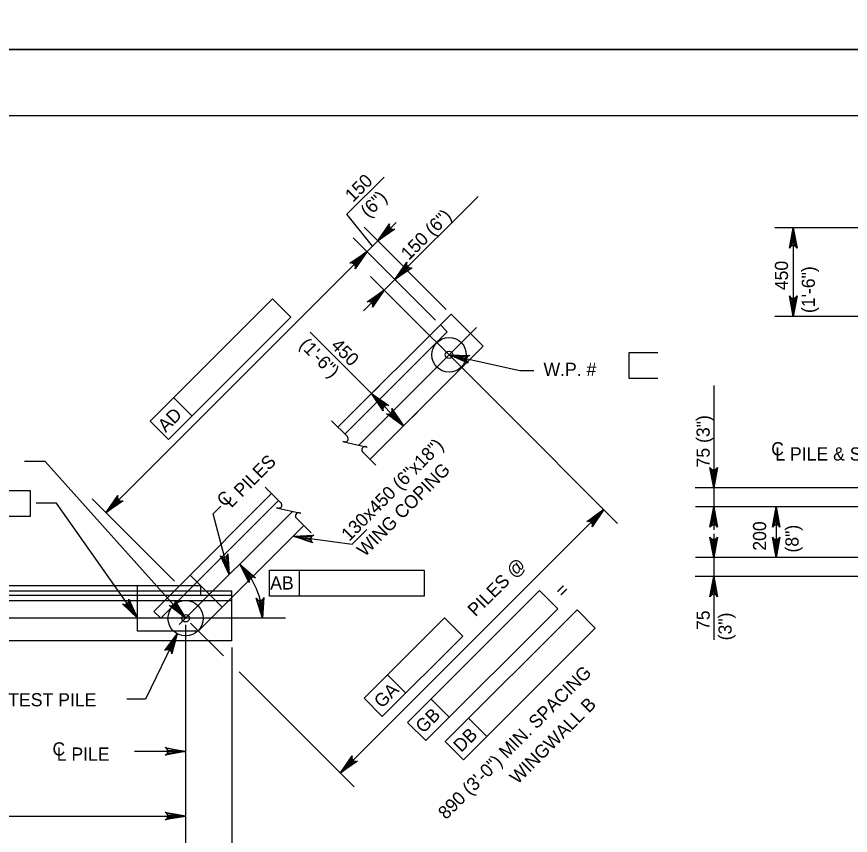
# Model space of a CAD drawing. Extents: x 635440 to 640306, y 296653 to 298484.
# Drawn here: x 638835.6 to 639025.5, y 297662.4 to 297849 of the extents above; entities that cross this region are included whole.
import ezdxf

# ---------------------------------------------------------------- set-up
doc = ezdxf.new("R2010")
doc.units = 0
for name, color, linetype in [('2', 7, 'Continuous'), ('4', 7, 'Continuous'), ('5', 7, 'Continuous'), ('PLT-BNDY', 7, 'Continuous')]:
    doc.layers.add(name, color=color, linetype=linetype)

msp = doc.modelspace()

# ---------------------------------------------------------------- linework, layer by layer
at = {"layer": '2'}
for p, q in [((638475.46, 297826.46), (639261.46, 297826.46)), ((638908.79, 297755.39), (638934.56, 297781.16)), ((638934.56, 297781.16), (638941.87, 297773.85)), ((638916.1, 297748.08), (638941.87, 297773.85)), ((638872.65, 297719.24), (638893.68, 297740.28)), ((638876.93, 297708.91), (638900.99, 297732.97)), ((638882.39, 297714.37), (638875.08, 297721.68)), ((638872.65, 297719.24), (638626.07, 297719.24)), ((638863.11, 297708.91), (638863.11, 297719.24)), ((638884.63, 297706.7), (638884.63, 297716.61)), ((638876.93, 297708.91), (638863.11, 297708.91)), ((638884.63, 297706.7), (638615.23, 297706.7))]:
    msp.add_line(p, q, dxfattribs=at)
msp.add_lwpolyline([(638863.11, 297711.86), (638844.66, 297738.11), (638840.05, 297738.11)], dxfattribs=at)
msp.add_lwpolyline([(638863.11, 297711.86), (638861.61, 297714.42), (638861.21, 297714.14)], close=True, dxfattribs=at)
at = {"layer": '4'}
for p, q in [((638910.35, 297753.82), (638933.69, 297777.16)), ((638932.13, 297778.72), (638933.69, 297777.16)), ((638868.4, 297711.86), (638895.24, 297738.71)), ((638615.23, 297718.1), (638884.63, 297718.1)), ((638872.65, 297719.24), (638866.83, 297713.43)), ((638877.54, 297719.24), (638872.65, 297719.24)), ((638877.54, 297717.03), (638877.54, 297719.24)), ((638884.63, 297716.61), (638884.63, 297718.1)), ((638884.63, 297717.03), (638615.23, 297717.03)), ((638615.23, 297715.88), (638884.63, 297715.88)), ((638868.4, 297711.86), (638866.83, 297713.43))]:
    msp.add_line(p, q, dxfattribs=at)
for points in [[(638934.1, 297771.88), (638950.22, 297768.33), (638953.44, 297768.33)], [(638874.08, 297711.86), (638842.11, 297747.55), (638837.34, 297747.55)], [(638898.58, 297730.56), (638911.99, 297728.73), (638915.35, 297732.08)]]:
    msp.add_lwpolyline(points, dxfattribs=at)
for points in [[(638934.1, 297771.88), (638936.93, 297771), (638937.03, 297771.49)], [(638898.58, 297730.56), (638901.47, 297729.92), (638901.54, 297730.4)], [(638874.08, 297711.86), (638872.29, 297714.22), (638871.93, 297713.9)]]:
    msp.add_lwpolyline(points, close=True, dxfattribs=at)
for centre, radius in [((638934.1, 297771.88), 3.94), ((638874.08, 297711.86), 4.02)]:
    msp.add_circle(centre, radius, dxfattribs=at)
at = {"layer": '5'}
for p, q in [((638910.85, 297803.91), (638919.35, 297812.41)), ((638921.78, 297789.07), (638940.7, 297807.99)), ((638916.64, 297796.64), (638910.85, 297803.91)), ((638917.86, 297797.86), (638922.03, 297802.04)), ((638933.47, 297782.25), (638914.73, 297801)), ((639034.02, 297800.84), (639008.36, 297800.84)), ((639012.51, 297800.84), (639012.51, 297780.65)), ((638931.04, 297779.81), (638912.29, 297798.56)), ((638912.99, 297792.99), (638917.86, 297797.86)), ((638855.94, 297735.95), (638915.42, 297795.43)), ((638913.33, 297793.34), (638911.25, 297791.25)), ((638931.04, 297779.81), (638918.65, 297792.2)), ((638916.21, 297789.77), (638945.21, 297760.77)), ((638921.78, 297789.07), (638919.34, 297786.63)), ((638919.34, 297786.63), (638914.63, 297781.92)), ((638866, 297756.8), (638893.84, 297784.64)), ((638893.84, 297784.64), (638898.02, 297780.46)), ((638870.18, 297752.62), (638898.02, 297780.46)), ((639029.65, 297780.65), (639008.36, 297780.65)), ((638916.44, 297763.04), (638902.45, 297777.03)), ((638913.53, 297751.31), (638940.33, 297778.12)), ((638975.11, 297772.39), (638981.71, 297772.39)), ((638975.11, 297766.49), (638975.11, 297772.39)), ((638917.04, 297763.64), (638919.57, 297766.17)), ((638981.71, 297766.49), (638975.11, 297766.49)), ((638994.42, 297764.9), (638994.42, 297737.24)), ((638871.35, 297762.15), (638875.52, 297757.97)), ((638923.74, 297755.73), (638916.44, 297763.04)), ((638945.21, 297760.77), (638972.5, 297733.48)), ((638924.34, 297756.33), (638926.88, 297758.86)), ((638866, 297756.8), (638870.18, 297752.62)), ((638907.35, 297756.83), (638910.93, 297753.24)), ((638914.37, 297749.81), (638917.42, 297746.75)), ((638797.48, 297740.95), (638838.69, 297740.95)), ((638838.69, 297740.95), (638838.69, 297735.04)), ((638892.23, 297741.73), (638895.81, 297738.14)), ((639029.65, 297741.57), (638990.17, 297741.57)), ((638871.56, 297720.33), (638852.81, 297739.08)), ((638880.38, 297735.66), (638882.11, 297737.39)), ((639057.05, 297737.24), (638990.25, 297737.24)), ((639008.64, 297737.24), (639008.64, 297725.7)), ((638872.62, 297710.4), (638898.42, 297736.2)), ((638884.03, 297721.81), (638880.38, 297735.66)), ((638909.35, 297676.59), (638969.37, 297736.61)), ((638994.42, 297736.2), (638994.42, 297732.04)), ((638838.69, 297735.04), (638797.48, 297735.04)), ((638899.25, 297734.71), (638902.65, 297731.31)), ((638871.56, 297720.33), (638859.17, 297732.72)), ((638994.42, 297731.12), (638994.42, 297730.73)), ((638994.42, 297730.9), (638994.42, 297721.38)), ((639046.96, 297725.7), (638990.25, 297725.7)), ((638994.42, 297725.7), (638994.42, 297706.95)), ((638893.17, 297722.83), (638928.47, 297722.83)), ((638893.17, 297716.92), (638893.17, 297722.83)), ((638900.01, 297716.92), (638900.01, 297722.83)), ((638928.47, 297722.83), (638928.47, 297716.92)), ((639029.65, 297721.38), (638990.17, 297721.38)), ((638924.62, 297688.13), (638954.69, 297718.2)), ((638954.69, 297718.2), (638958.86, 297714.02)), ((638928.47, 297716.92), (638893.17, 297716.92)), ((638928.79, 297683.96), (638958.86, 297714.02)), ((638933.19, 297683.74), (638963.26, 297713.81)), ((638963.26, 297713.81), (638967.43, 297709.63)), ((638896.85, 297711.86), (638603.94, 297711.86)), ((638875.17, 297710.77), (638882.69, 297703.26)), ((638914.73, 297693.62), (638933.07, 297711.96)), ((638933.07, 297711.96), (638937.25, 297707.79)), ((638874.08, 297710.32), (638874.08, 297650.07)), ((638937.37, 297679.57), (638967.43, 297709.63)), ((638872.19, 297708.31), (638864.92, 297693.42)), ((638918.9, 297689.44), (638937.25, 297707.79)), ((638884.63, 297705.16), (638884.63, 297635.92)), ((638886.3, 297699.64), (638912.48, 297673.46)), ((638920.08, 297698.97), (638924.25, 297694.79)), ((638864.92, 297693.42), (638860.72, 297693.42)), ((638914.73, 297693.62), (638918.9, 297689.44)), ((638929.97, 297693.48), (638934.14, 297689.3)), ((638924.62, 297688.13), (638928.79, 297683.96)), ((638938.54, 297689.09), (638942.71, 297684.91)), ((638933.19, 297683.74), (638937.37, 297679.57)), ((638874.08, 297681.51), (638862.46, 297681.51)), ((638624.44, 297666.75), (638874.08, 297666.75))]:
    msp.add_line(p, q, dxfattribs=at)
for points in [[(638917.86, 297797.86), (638920.54, 297801.78), (638920.46, 297801.35), (638920.55, 297801), (638920.73, 297800.74), (638920.99, 297800.55), (638921.34, 297800.46), (638921.77, 297800.54), (638917.86, 297797.86), (638921.34, 297800.46), (638920.99, 297800.55), (638917.86, 297797.86), (638920.73, 297800.74), (638920.55, 297801), (638917.86, 297797.86), (638920.46, 297801.35)], [(639012.51, 297800.84), (639013.39, 297796.18), (639013.14, 297796.54), (639012.83, 297796.72), (639012.51, 297796.77), (639012.2, 297796.72), (639011.89, 297796.54), (639011.64, 297796.18), (639012.51, 297800.84), (639011.89, 297796.54), (639012.2, 297796.72), (639012.51, 297800.84), (639012.51, 297796.77), (639012.83, 297796.72), (639012.51, 297800.84), (639013.14, 297796.54)], [(638915.42, 297795.43), (638912.74, 297791.51), (638912.82, 297791.94), (638912.73, 297792.3), (638912.55, 297792.55), (638912.29, 297792.74), (638911.94, 297792.83), (638911.51, 297792.75), (638915.42, 297795.43), (638911.94, 297792.83), (638912.29, 297792.74), (638915.42, 297795.43), (638912.55, 297792.55), (638912.73, 297792.3), (638915.42, 297795.43), (638912.82, 297791.94)], [(638921.78, 297789.07), (638924.46, 297792.98), (638924.38, 297792.56), (638924.47, 297792.2), (638924.65, 297791.95), (638924.91, 297791.76), (638925.26, 297791.67), (638925.69, 297791.75), (638921.78, 297789.07), (638925.26, 297791.67), (638924.91, 297791.76), (638921.78, 297789.07), (638924.65, 297791.95), (638924.47, 297792.2), (638921.78, 297789.07), (638924.38, 297792.56)], [(638919.34, 297786.63), (638916.67, 297782.72), (638916.74, 297783.15), (638916.65, 297783.5), (638916.47, 297783.76), (638916.21, 297783.94), (638915.86, 297784.03), (638915.43, 297783.96), (638919.34, 297786.63), (638915.86, 297784.03), (638916.21, 297783.94), (638919.34, 297786.63), (638916.47, 297783.76), (638916.65, 297783.5), (638919.34, 297786.63), (638916.74, 297783.15)], [(639012.51, 297780.65), (639011.64, 297785.31), (639011.89, 297784.95), (639012.2, 297784.77), (639012.51, 297784.71), (639012.83, 297784.77), (639013.14, 297784.95), (639013.39, 297785.31), (639012.51, 297780.65), (639013.14, 297784.95), (639012.83, 297784.77), (639012.51, 297780.65), (639012.51, 297784.71), (639012.2, 297784.77), (639012.51, 297780.65), (639011.89, 297784.95)], [(638934.1, 297771.88), (638938.84, 297771.73), (638938.43, 297771.57), (638938.18, 297771.3), (638938.06, 297771.01), (638938.05, 297770.69), (638938.16, 297770.34), (638938.46, 297770.02), (638934.1, 297771.88), (638938.16, 297770.34), (638938.05, 297770.69), (638934.1, 297771.88), (638938.06, 297771.01), (638938.18, 297771.3), (638934.1, 297771.88), (638938.43, 297771.57)], [(638916.44, 297763.04), (638920.35, 297760.36), (638919.92, 297760.44), (638919.57, 297760.35), (638919.31, 297760.16), (638919.13, 297759.91), (638919.04, 297759.55), (638919.12, 297759.12), (638916.44, 297763.04), (638919.04, 297759.55), (638919.13, 297759.91), (638916.44, 297763.04), (638919.31, 297760.16), (638919.57, 297760.35), (638916.44, 297763.04), (638919.92, 297760.44)], [(638923.74, 297755.73), (638919.83, 297758.41), (638920.26, 297758.33), (638920.61, 297758.42), (638920.87, 297758.6), (638921.05, 297758.86), (638921.15, 297759.21), (638921.07, 297759.64), (638923.74, 297755.73), (638921.15, 297759.21), (638921.05, 297758.86), (638923.74, 297755.73), (638920.87, 297758.6), (638920.61, 297758.42), (638923.74, 297755.73), (638920.26, 297758.33)], [(638910.25, 297752.06), (638909.9, 297752.13), (638915.44, 297750.87), (638915.07, 297750.96)], [(638994.42, 297741.57), (638993.55, 297746.23), (638993.79, 297745.87), (638994.11, 297745.68), (638994.42, 297745.63), (638994.73, 297745.68), (638995.04, 297745.87), (638995.29, 297746.23), (638994.42, 297741.57), (638995.04, 297745.87), (638994.73, 297745.68), (638994.42, 297741.57), (638994.42, 297745.63), (638994.11, 297745.68), (638994.42, 297741.57), (638993.79, 297745.87)], [(638855.94, 297735.95), (638858.62, 297739.86), (638858.54, 297739.43), (638858.63, 297739.08), (638858.82, 297738.82), (638859.08, 297738.64), (638859.43, 297738.55), (638859.86, 297738.63), (638855.94, 297735.95), (638859.43, 297738.55), (638859.08, 297738.64), (638855.94, 297735.95), (638858.82, 297738.82), (638858.63, 297739.08), (638855.94, 297735.95), (638858.54, 297739.43)], [(638994.42, 297737.24), (638995.29, 297732.58), (638995.04, 297732.94), (638994.73, 297733.12), (638994.42, 297733.18), (638994.11, 297733.12), (638993.79, 297732.94), (638993.55, 297732.58), (638994.42, 297737.24), (638993.79, 297732.94), (638994.11, 297733.12), (638994.42, 297737.24), (638994.42, 297733.18), (638994.73, 297733.12), (638994.42, 297737.24), (638995.04, 297732.94)], [(639008.64, 297737.24), (639009.51, 297732.58), (639009.27, 297732.94), (639008.95, 297733.12), (639008.64, 297733.18), (639008.33, 297733.12), (639008.02, 297732.94), (639007.77, 297732.58), (639008.64, 297737.24), (639008.02, 297732.94), (639008.33, 297733.12), (639008.64, 297737.24), (639008.64, 297733.18), (639008.95, 297733.12), (639008.64, 297737.24), (639009.27, 297732.94)], [(638895.13, 297736.95), (638894.78, 297737.03), (638900.32, 297735.77), (638899.95, 297735.85)], [(638969.37, 297736.61), (638966.69, 297732.69), (638966.77, 297733.12), (638966.68, 297733.48), (638966.5, 297733.73), (638966.24, 297733.92), (638965.89, 297734.01), (638965.46, 297733.93), (638969.37, 297736.61), (638965.89, 297734.01), (638966.24, 297733.92), (638969.37, 297736.61), (638966.5, 297733.73), (638966.68, 297733.48), (638969.37, 297736.61), (638966.77, 297733.12)], [(638898.58, 297730.56), (638903.32, 297730.8), (638902.93, 297730.6), (638902.7, 297730.31), (638902.61, 297730.01), (638902.62, 297729.69), (638902.76, 297729.36), (638903.08, 297729.07), (638898.58, 297730.56), (638902.76, 297729.36), (638902.62, 297729.69), (638898.58, 297730.56), (638902.61, 297730.01), (638902.7, 297730.31), (638898.58, 297730.56), (638902.93, 297730.6)], [(638994.42, 297725.7), (638993.55, 297730.37), (638993.79, 297730.01), (638994.11, 297729.82), (638994.42, 297729.77), (638994.73, 297729.82), (638995.04, 297730.01), (638995.29, 297730.37), (638994.42, 297725.7), (638995.04, 297730.01), (638994.73, 297729.82), (638994.42, 297725.7), (638994.42, 297729.77), (638994.11, 297729.82), (638994.42, 297725.7), (638993.79, 297730.01)], [(639008.64, 297725.7), (639007.77, 297730.37), (639008.02, 297730.01), (639008.33, 297729.82), (639008.64, 297729.77), (639008.95, 297729.82), (639009.27, 297730.01), (639009.51, 297730.37), (639008.64, 297725.7), (639009.27, 297730.01), (639008.95, 297729.82), (639008.64, 297725.7), (639008.64, 297729.77), (639008.33, 297729.82), (639008.64, 297725.7), (639008.02, 297730.01)], [(638884.03, 297721.81), (638882, 297726.1), (638882.33, 297725.82), (638882.68, 297725.72), (638882.99, 297725.74), (638883.28, 297725.88), (638883.54, 297726.13), (638883.69, 297726.54), (638884.03, 297721.81), (638883.54, 297726.13), (638883.28, 297725.88), (638884.03, 297721.81), (638882.99, 297725.74), (638882.68, 297725.72), (638884.03, 297721.81), (638882.33, 297725.82)], [(638886.43, 297724.21), (638889.97, 297721.06), (638889.55, 297721.19), (638889.19, 297721.14), (638888.91, 297720.99), (638888.7, 297720.76), (638888.57, 297720.42), (638888.59, 297719.99), (638886.43, 297724.21), (638888.57, 297720.42), (638888.7, 297720.76), (638886.43, 297724.21), (638888.91, 297720.99), (638889.19, 297721.14), (638886.43, 297724.21), (638889.55, 297721.19)], [(638994.42, 297721.38), (638995.29, 297716.72), (638995.04, 297717.08), (638994.73, 297717.26), (638994.42, 297717.32), (638994.11, 297717.26), (638993.79, 297717.08), (638993.55, 297716.72), (638994.42, 297721.38), (638993.79, 297717.08), (638994.11, 297717.26), (638994.42, 297721.38), (638994.42, 297717.32), (638994.73, 297717.26), (638994.42, 297721.38), (638995.04, 297717.08)], [(638863.11, 297711.86), (638859.71, 297715.17), (638860.12, 297715.02), (638860.49, 297715.05), (638860.77, 297715.19), (638861, 297715.41), (638861.15, 297715.74), (638861.14, 297716.18), (638863.11, 297711.86), (638861.15, 297715.74), (638861, 297715.41), (638863.11, 297711.86), (638860.77, 297715.19), (638860.49, 297715.05), (638863.11, 297711.86), (638860.12, 297715.02)], [(638891.57, 297711.87), (638890.19, 297716.41), (638890.48, 297716.08), (638890.81, 297715.93), (638891.12, 297715.91), (638891.43, 297716), (638891.72, 297716.21), (638891.93, 297716.6), (638891.57, 297711.87), (638891.72, 297716.21), (638891.43, 297716), (638891.57, 297711.87), (638891.12, 297715.91), (638890.81, 297715.93), (638891.57, 297711.87), (638890.48, 297716.08)], [(638874.08, 297711.86), (638870.32, 297714.75), (638870.74, 297714.65), (638871.1, 297714.72), (638871.37, 297714.89), (638871.57, 297715.14), (638871.68, 297715.48), (638871.62, 297715.92), (638874.08, 297711.86), (638871.68, 297715.48), (638871.57, 297715.14), (638874.08, 297711.86), (638871.37, 297714.89), (638871.1, 297714.72), (638874.08, 297711.86), (638870.74, 297714.65)], [(638872.19, 297708.31), (638870.93, 297703.74), (638870.87, 297704.17), (638870.67, 297704.48), (638870.41, 297704.66), (638870.11, 297704.75), (638869.74, 297704.72), (638869.36, 297704.51), (638872.19, 297708.31), (638869.74, 297704.72), (638870.11, 297704.75), (638872.19, 297708.31), (638870.41, 297704.66), (638870.67, 297704.48), (638872.19, 297708.31), (638870.87, 297704.17)], [(638874.08, 297681.51), (638869.42, 297680.64), (638869.78, 297680.89), (638869.96, 297681.2), (638870.02, 297681.51), (638869.96, 297681.82), (638869.78, 297682.14), (638869.42, 297682.38), (638874.08, 297681.51), (638869.78, 297682.14), (638869.96, 297681.82), (638874.08, 297681.51), (638870.02, 297681.51), (638869.96, 297681.2), (638874.08, 297681.51), (638869.78, 297680.89)], [(638909.35, 297676.59), (638912.03, 297680.5), (638911.95, 297680.07), (638912.04, 297679.72), (638912.23, 297679.46), (638912.48, 297679.28), (638912.84, 297679.19), (638913.27, 297679.27), (638909.35, 297676.59), (638912.84, 297679.19), (638912.48, 297679.28), (638909.35, 297676.59), (638912.23, 297679.46), (638912.04, 297679.72), (638909.35, 297676.59), (638911.95, 297680.07)], [(638874.08, 297666.75), (638869.42, 297665.88), (638869.78, 297666.13), (638869.96, 297666.44), (638870.02, 297666.75), (638869.96, 297667.07), (638869.78, 297667.38), (638869.42, 297667.63), (638874.08, 297666.75), (638869.78, 297667.38), (638869.96, 297667.07), (638874.08, 297666.75), (638870.02, 297666.75), (638869.96, 297666.44), (638874.08, 297666.75), (638869.78, 297666.13)]]:
    msp.add_lwpolyline(points, dxfattribs=at)
for points in [[(638919.6, 297800.3), (638920.29, 297799.6), (638917.86, 297797.86)], [(639012.05, 297798.07), (639012.98, 297798.07), (639012.51, 297800.84)], [(638912.99, 297793.69), (638913.68, 297792.99), (638915.42, 297795.43)], [(638923.52, 297791.51), (638924.22, 297790.81), (638921.78, 297789.07)], [(638916.91, 297784.89), (638917.6, 297784.2), (638919.34, 297786.63)], [(639012.05, 297783.42), (639012.98, 297783.42), (639012.51, 297780.65)], [(638918.87, 297761.3), (638918.18, 297760.6), (638916.44, 297763.04)], [(638922.01, 297758.16), (638921.31, 297757.47), (638923.74, 297755.73)], [(638857.68, 297738.38), (638858.38, 297737.69), (638855.94, 297735.95)], [(638966.93, 297734.87), (638967.63, 297734.17), (638969.37, 297736.61)], [(638883.75, 297724.8), (638882.8, 297724.54), (638884.03, 297721.81)], [(638871.13, 297681.02), (638871.13, 297682), (638874.08, 297681.51)], [(638911.09, 297679.03), (638911.79, 297678.33), (638909.35, 297676.59)], [(638871.13, 297667.25), (638871.13, 297666.26), (638874.08, 297666.75)]]:
    msp.add_lwpolyline(points, close=True, dxfattribs=at)
for centre in [(638934.1, 297771.88), (638874.08, 297711.86)]:
    msp.add_circle(centre, 0.85, dxfattribs=at)
for centre, radius, start, end in [((638910.43, 297752.74), 0.71, 255, 45), ((638914.91, 297750.26), 0.71, 77.1328, 219.6714), ((638895.31, 297737.64), 0.71, 255, 45), ((638899.79, 297735.16), 0.71, 77.1328, 219.6714), ((638874.25, 297711.86), 17.32, 0.0009, 45.394)]:
    msp.add_arc(centre, radius, start, end, dxfattribs=at)
at = {"layer": 'PLT-BNDY'}
for points in [[(638435.46, 298435.46), (639276.46, 298435.46), (639276.46, 297841.46), (638435.46, 297841.46)], [(638435.46, 297841.46), (639276.46, 297841.46), (639276.46, 297247.46), (638435.46, 297247.46)]]:
    msp.add_lwpolyline(points, close=True, dxfattribs=at)

# ---------------------------------------------------------------- texts
at = {"layer": '5'}
for s, height, rotation, p in [('150', 3, 45, (638912.2, 297806.52)), ('(6")', 3, 45, (638915.74, 297802.98)), ('150 (6")', 3, 45, (638924.92, 297793.29)), ('450', 3, 90, (639011.34, 297786.62)), ('(1\'-6")', 3, 90, (639017.46, 297781.41)), ('(1\'-6")', 3, 315, (638899.79, 297773.95)), ('450', 3, 315, (638907, 297773.8)), ('AD', 3, 45, (638869.55, 297754.05)), ('75 (3")', 3, 90, (638993.49, 297746.23)), ('130x450 (6"x18")', 3.0001, 45, (638911.35, 297729.26)), ('L PILES', 3, 45, (638884.5, 297736.89)), ('WING COPING', 3.0001, 45, (638914.89, 297725.72)), ('C', 3, 45, (638882.97, 297737.06)), ('200', 3, 90, (639006.35, 297727.25)), ('(8")', 3, 90, (639013.74, 297726.83)), ('PILES @', 3, 44.9382, (638940.12, 297712.03)), ('=', 3, 44.9382, (638960.08, 297716.38)), ('75', 3, 90, (638993.49, 297709.18)), ('(3")', 3, 90, (638998.49, 297706.82)), ('890 (3\'-0") MIN. SPACING', 3.0001, 45, (638933.41, 297665.82)), ('GA', 3, 44.9382, (638918.8, 297691.19)), ('WINGWALL B', 3, 45, (638949.71, 297673.88)), ('GB', 3, 44.9382, (638928.25, 297685.47)), ('DB', 3, 44.9382, (638936.86, 297681.11))]:
    msp.add_text(s, height=height, rotation=rotation, dxfattribs=at).set_placement(p)
for s, height, p in [('W.P. #', 3, (638955.63, 297767.09)), ('C', 3, (639007.51, 297748.98)), ('L PILE & SPLICE', 3.0001, (639008.45, 297747.8)), ('AB', 3, (638893.35, 297718.4)), ('TEST PILE', 3, (638833.67, 297691.78)), ('C', 3, (638843.74, 297680.58)), ('L PILE', 3, (638844.71, 297679.4))]:
    msp.add_text(s, height=height, dxfattribs=at).set_placement(p)

doc.saveas('drawing.dxf')
